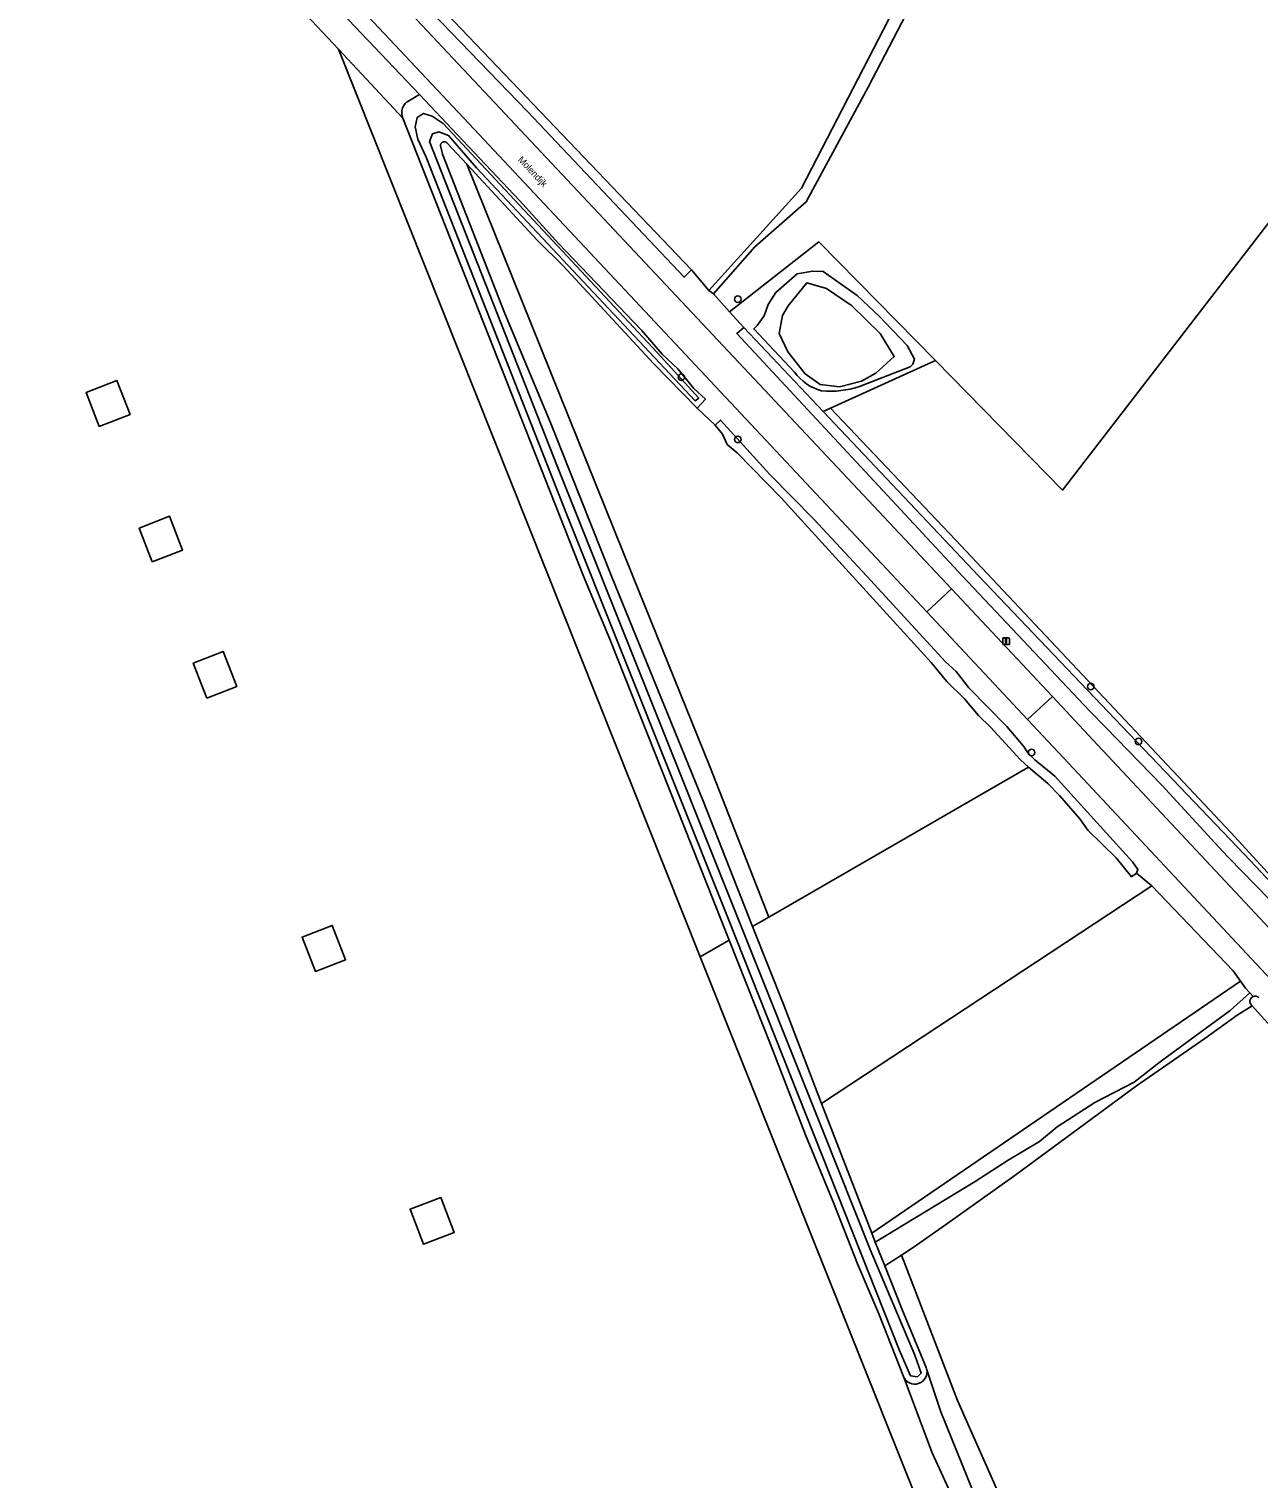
# Model space of a CAD drawing. Extents: x 164494 to 166241, y 382475 to 384495.
# Drawn here: x 165112.8 to 165297.4, y 384114.4 to 384332.1 of the extents above; entities that cross this region are included whole.
import ezdxf

# ---------------------------------------------------------------- set-up
doc = ezdxf.new("R2010")
doc.units = 0
for name, color, linetype in [('IMGEO_Boom', 7, 'Continuous'), ('IMGEO_Erf', 7, 'Continuous'), ('IMGEO_Grasland_agrarisch', 7, 'Continuous'), ('IMGEO_Grasland_overig', 7, 'Continuous'), ('IMGEO_Groenvoorziening', 7, 'Continuous'), ('IMGEO_Hek', 7, 'Continuous'), ('IMGEO_Lichtmast', 7, 'Continuous'), ('IMGEO_Loofbos', 7, 'Continuous'), ('IMGEO_Meer_plas_ven_vijver', 7, 'Continuous'), ('IMGEO_Oever', 7, 'Continuous'), ('IMGEO_Openbare_ruimte_label', 7, 'Continuous'), ('IMGEO_Pand', 7, 'Continuous'), ('IMGEO_Rijbaan_lokaal_gesloten', 7, 'Continuous'), ('IMGEO_Waterloop', 7, 'Continuous')]:
    doc.layers.add(name, color=color, linetype=linetype)

msp = doc.modelspace()

# ---------------------------------------------------------------- linework, layer by layer
at = {"layer": 'IMGEO_Boom'}
for centre in [(165219.18, 384291.57), (165210.71, 384279.85), (165219.2, 384270.52), (165272.16, 384233.41), (165279.34, 384225.17), (165263.29, 384223.52)]:
    msp.add_circle(centre, 0.489, dxfattribs=at)
at = {"layer": 'IMGEO_Erf'}
msp.add_lwpolyline([(165058.45, 383934.76), (165225.03, 384001.82), (165229.53, 384009.13), (165229.49, 384009.32), (165229.72, 384009.7), (165231.84, 384013.12), (165231.96, 384013.3), (165232.95, 384013.71), (165234.05, 384014.16), (165234.97, 384014.54), (165251.9, 384021.52), (165224.07, 384092.01), (165249.77, 384102.11), (165213.54, 384192.85), (165159.24, 384329.08), (165128.69, 384361.62), (165128.46, 384361.87), (165121.19, 384360.32), (165097.67, 384355.37)], dxfattribs=at)
for points in [[(165123.33, 384272.45), (165121.34, 384277.57), (165125.98, 384279.37), (165127.96, 384274.26)], [(165131.29, 384252.13), (165129.32, 384257.2), (165133.88, 384258.97), (165135.84, 384253.9)], [(165139.46, 384231.69), (165137.44, 384236.92), (165141.95, 384238.67), (165143.97, 384233.43)], [(165153.78, 384195.81), (165158.3, 384197.55), (165160.3, 384192.38), (165155.77, 384190.64)], [(165169.99, 384154.95), (165174.62, 384156.7), (165176.61, 384151.46), (165171.99, 384149.7)]]:
    msp.add_lwpolyline(points, close=True, dxfattribs=at)
at = {"layer": 'IMGEO_Grasland_agrarisch'}
for points in [[(165254.18, 384357.46), (165254.34, 384357.92), (165219.22, 384399.74), (165132.98, 384384.35), (165141.95, 384371.97), (165145.05, 384368.61), (165145.22, 384368.44), (165150.26, 384361.6), (165171.18, 384338.98), (165212.21, 384295.98), (165214.85, 384292.89), (165228.77, 384308.21)], [(165281.32, 384203.5), (165279.02, 384205.42), (165278.29, 384204.86), (165275.96, 384207.68), (165271.71, 384211.86), (165270.52, 384213.57), (165267.49, 384217.07), (165265.74, 384218.88), (165262.8, 384221.32), (165223.85, 384198.81), (165221.41, 384197.4), (165226.07, 384185.57), (165231.77, 384170.82)], [(165231.77, 384170.82), (165239.29, 384151.37), (165294.64, 384189.17), (165293.54, 384190.72), (165281.32, 384203.5)]]:
    msp.add_lwpolyline(points, close=True, dxfattribs=at)
for points in [[(165317.48, 384327.15), (165267.93, 384262.9), (165248.84, 384282.34), (165233.08, 384275.18), (165251.87, 384255.44), (165293.19, 384211.49), (165316.39, 384186.25)], [(165324.58, 384114.29), (165325.92, 384115.35), (165347.39, 384132.2), (165335.97, 384142.71), (165320.44, 384159.32), (165315.88, 384164.36), (165309.08, 384171.59), (165305.99, 384174.88), (165304.75, 384176.21), (165296.41, 384185.48), (165294.17, 384184.07), (165289.31, 384180.6), (165279.06, 384173.47), (165260.79, 384160), (165250.35, 384152.62), (165245.53, 384149.21), (165243.74, 384148.06), (165245.46, 384143.65), (165252.14, 384126.21), (165259.36, 384109.98)]]:
    msp.add_lwpolyline(points, dxfattribs=at)
at = {"layer": 'IMGEO_Grasland_overig'}
for points in [[(165232.02, 384274.7), (165233.08, 384275.18), (165248.84, 384282.34), (165231.34, 384300.16), (165217.95, 384289.68), (165220.11, 384287.31)], [(165233.08, 384275.18), (165232.02, 384274.7), (165255.37, 384250), (165275.8, 384228.59), (165295.27, 384208.19), (165305.21, 384197.62), (165322.53, 384178.74), (165325.13, 384175.54), (165325.83, 384175.2), (165326.06, 384175.76), (165321.54, 384180.91), (165316.39, 384186.25), (165293.19, 384211.49), (165251.87, 384255.44)], [(165247.53, 384131.01), (165249.67, 384124.52), (165256.93, 384106.64), (165258.22, 384103.1), (165258.28, 384102.33), (165257.62, 384100.16), (165260.84, 384103.1), (165261.01, 384104.04), (165260.63, 384106.52), (165259.36, 384109.98), (165252.14, 384126.21), (165245.46, 384143.65), (165243.74, 384148.06), (165241.24, 384146.44), (165243.81, 384140), (165247.47, 384131.21)]]:
    msp.add_lwpolyline(points, close=True, dxfattribs=at)
for points in [[(165227.71, 384280.63), (165221.58, 384287.11), (165222.11, 384287.59), (165223.16, 384289.09), (165223.76, 384290.79), (165224.87, 384292.55), (165228.08, 384295.36), (165230.43, 384295.79)], [(165230.43, 384295.79), (165231.99, 384295.7), (165237.12, 384292.1), (165240.45, 384288.98), (165244.61, 384284.63), (165245.69, 384282.56), (165245.46, 384281.81), (165245.08, 384281.41), (165237.47, 384278.45)]]:
    msp.add_lwpolyline(points, dxfattribs=at)
for centre, radius, start, end in [((165233.63, 384284.8), 7.24, 215.1594, 255.041), ((165233.02, 384292.32), 14.57, 265.044, 287.7993)]:
    msp.add_arc(centre, radius, start, end, dxfattribs=at)
at = {"layer": 'IMGEO_Groenvoorziening'}
for points in [[(165125.84, 384370.22), (165121.47, 384369.32), (165128.46, 384361.87), (165128.69, 384361.62), (165159.24, 384329.08), (165168.89, 384318.74), (165168.83, 384318.92), (165168.78, 384319.11), (165168.75, 384319.31), (165168.74, 384319.5), (165168.75, 384319.7), (165168.77, 384319.89), (165168.82, 384320.09), (165168.87, 384320.27), (165168.95, 384320.45), (165169.04, 384320.63), (165169.14, 384320.79), (165169.26, 384320.95), (165169.39, 384321.1), (165171.41, 384322.29)], [(165219.09, 384268.52), (165217.58, 384269.73), (165216.89, 384271.32), (165215.78, 384272.64), (165213.06, 384275.2), (165206.53, 384281.93), (165192.95, 384296.56), (165189.06, 384300.45), (165178.53, 384311.81), (165203.45, 384250), (165214.98, 384221.39), (165223.85, 384198.81), (165262.8, 384221.32), (165261.63, 384222.41), (165257.13, 384227.32), (165255.32, 384229.07), (165253.22, 384231.55), (165250.54, 384234.16), (165248.2, 384237.04), (165236.38, 384250), (165225.68, 384261.74)]]:
    msp.add_lwpolyline(points, close=True, dxfattribs=at)
for points in [[(165125.84, 384370.22), (165171.41, 384322.29), (165177.05, 384316.3), (165186.4, 384306.37), (165192.3, 384299.89), (165204.72, 384286.92), (165207.82, 384283.32), (165210.2, 384281.1), (165212.58, 384278.17), (165214.31, 384276.57), (165213.06, 384275.2), (165215.78, 384272.64), (165216.57, 384273.42), (165223.99, 384265.27), (165230.58, 384258.54), (165238.55, 384250), (165250.38, 384237.11), (165251.97, 384235.66), (165253.85, 384233.24), (165259.59, 384227.44), (165262.05, 384224.47), (165262.72, 384223.44), (165263.77, 384222.42), (165266.79, 384219.98), (165278.45, 384207.1), (165279.24, 384205.95), (165279.02, 384205.42), (165281.32, 384203.5), (165293.54, 384190.72), (165294.64, 384189.17), (165295.4, 384188.12), (165296.05, 384187.42), (165296.57, 384186.89)], [(165149.92, 384355.97), (165251.27, 384248.07), (165266.44, 384231.9), (165272.49, 384225.43), (165349.9, 384142.75), (165389.4, 384100.28)], [(165304.9, 384195.4), (165292.88, 384207.71), (165291.99, 384208.63), (165282.82, 384218.63), (165274.42, 384227.27), (165271.99, 384229.76), (165252.93, 384250), (165219.02, 384286.4), (165220.11, 384287.31), (165217.95, 384289.68), (165215.52, 384292.35), (165214.85, 384292.89), (165212.21, 384295.98), (165211.13, 384294.85), (165187.62, 384319.76), (165167.54, 384340.58)], [(165262.69, 384228.45), (165247.55, 384244.62), (165178.79, 384317.94), (165158.15, 384339.95)], [(165392.96, 384088.88), (165346.21, 384139.18), (165268.81, 384221.91), (165262.69, 384228.45)], [(165253.82, 384106.45), (165248.37, 384118.39), (165244.04, 384129.85), (165240.35, 384139.25), (165237.16, 384146.73), (165233.6, 384155.8), (165229.33, 384166.13), (165224.13, 384179.56), (165217.87, 384195.35), (165213.54, 384192.85), (165249.77, 384102.11)], [(165244.04, 384129.85), (165248.37, 384118.39), (165253.82, 384106.45)], [(165257.62, 384100.16), (165258.28, 384102.33), (165258.22, 384103.1), (165256.93, 384106.64), (165249.67, 384124.52), (165247.53, 384131.01)]]:
    msp.add_lwpolyline(points, dxfattribs=at)
for centre, radius, start, end in [((165296.85, 384186.14), 0.799, 44.3556, 111.0539), ((165245.75, 384130.53), 1.84, 201.7636, 15.0275)]:
    msp.add_arc(centre, radius, start, end, dxfattribs=at)
at = {"layer": 'IMGEO_Hek'}
for points in [[(165159.24, 384329.08), (165128.69, 384361.62)], [(165213.54, 384192.85), (165159.24, 384329.08)], [(165178.53, 384311.81), (165203.45, 384250), (165214.98, 384221.39), (165223.85, 384198.81)], [(165224.07, 384092.01), (165249.77, 384102.11), (165213.54, 384192.85)], [(165294.64, 384189.17), (165239.29, 384151.37)], [(165243.74, 384148.06), (165245.46, 384143.65), (165252.14, 384126.21), (165259.36, 384109.98)]]:
    msp.add_lwpolyline(points, dxfattribs=at)
at = {"layer": 'IMGEO_Lichtmast'}
for p, q in [((165258.96, 384239.81), (165258.96, 384240.61)), ((165258.96, 384240.61), (165258.96, 384239.81)), ((165259.06, 384240.71), (165259.85, 384240.71)), ((165259.85, 384240.71), (165259.06, 384240.71)), ((165259.95, 384240.61), (165259.95, 384239.81)), ((165259.95, 384239.81), (165259.95, 384240.61)), ((165259.85, 384239.71), (165259.06, 384239.71)), ((165259.06, 384239.71), (165259.85, 384239.71))]:
    msp.add_line(p, q, dxfattribs=at)
msp.add_lwpolyline([(165259.38, 384240.58), (165259.53, 384240.58), (165259.53, 384239.83), (165259.38, 384239.83), (165259.38, 384240.58)], dxfattribs=at)
for centre, start, end in [((165259.06, 384240.61), 90, 180), ((165259.06, 384240.61), 90, 180), ((165259.85, 384240.61), 0, 90), ((165259.85, 384240.61), 360, 90), ((165259.06, 384239.81), 180, 270), ((165259.06, 384239.81), 180, 270), ((165259.85, 384239.81), 270, 0), ((165259.85, 384239.81), 270, 0)]:
    msp.add_arc(centre, 0.1, start, end, dxfattribs=at)
at = {"layer": 'IMGEO_Loofbos'}
for points in [[(165257.7, 384359.88), (165238.75, 384323.39), (165229.45, 384306.17), (165221.72, 384299.42), (165215.52, 384292.35), (165217.95, 384289.68), (165231.34, 384300.16), (165248.84, 384282.34), (165267.93, 384262.9), (165317.48, 384327.15), (165319.12, 384329.28), (165345.49, 384364.26)], [(165296.05, 384187.42), (165293.09, 384184.78), (165282.6, 384177.08), (165278.7, 384174.04), (165272.78, 384170.96), (165267.11, 384167.33), (165264.47, 384165.1), (165259.77, 384162.29), (165254.84, 384159.1), (165239.81, 384150.02), (165240.26, 384148.89), (165241.24, 384146.44), (165243.74, 384148.06), (165245.53, 384149.21), (165250.35, 384152.62), (165260.79, 384160), (165279.06, 384173.47), (165289.31, 384180.6), (165294.17, 384184.07), (165296.41, 384185.48), (165296.32, 384185.55)], [(165296.57, 384186.89), (165296.05, 384187.42)]]:
    msp.add_lwpolyline(points, dxfattribs=at)
for points in [[(165217.87, 384195.35), (165199.96, 384240.51), (165196.02, 384250), (165168.89, 384318.74), (165159.24, 384329.08), (165213.54, 384192.85)], [(165223.85, 384198.81), (165214.98, 384221.39), (165203.45, 384250), (165178.53, 384311.81), (165175.6, 384314.93), (165175.58, 384314.98), (165175.54, 384315.01), (165175.51, 384315.05), (165175.47, 384315.08), (165175.43, 384315.11), (165175.38, 384315.14), (165175.34, 384315.16), (165175.29, 384315.17), (165175.24, 384315.18), (165175.19, 384315.19), (165175.14, 384315.2), (165175.09, 384315.2), (165175.04, 384315.19), (165174.99, 384315.18), (165174.94, 384315.17), (165174.89, 384315.15), (165174.85, 384315.13), (165174.8, 384315.1), (165174.77, 384315.07), (165174.73, 384315.04), (165174.69, 384315), (165174.66, 384314.96), (165174.63, 384314.92), (165174.61, 384314.88), (165174.59, 384314.83), (165174.57, 384314.78), (165174.56, 384314.73), (165174.55, 384314.68), (165174.55, 384314.63), (165174.55, 384314.58), (165174.56, 384314.53), (165174.57, 384314.48), (165174.58, 384314.43), (165174.86, 384313.34), (165184.22, 384289.44), (165191.12, 384272.92), (165200.21, 384250), (165213.95, 384216.36), (165221.41, 384197.4)], [(165239.29, 384151.37), (165239.81, 384150.02), (165254.84, 384159.1), (165259.77, 384162.29), (165264.47, 384165.1), (165267.11, 384167.33), (165272.78, 384170.96), (165278.7, 384174.04), (165282.6, 384177.08), (165293.09, 384184.78), (165296.05, 384187.42), (165295.4, 384188.12), (165294.64, 384189.17)]]:
    msp.add_lwpolyline(points, close=True, dxfattribs=at)
msp.add_arc((165296.85, 384186.15), 0.797, 111.1183, 228.3097, dxfattribs=at)
at = {"layer": 'IMGEO_Meer_plas_ven_vijver'}
msp.add_lwpolyline([(165240.55, 384286.42), (165236.27, 384290.64), (165232.5, 384293.18), (165229.56, 384294.02), (165226.74, 384290.56), (165225.89, 384289.13), (165225.39, 384286.42), (165226.67, 384283.66), (165229.29, 384280.35), (165231.54, 384278.74), (165234.44, 384278.42), (165237.75, 384279.25), (165239.89, 384280.47), (165242.66, 384282.95)], close=True, dxfattribs=at)
at = {"layer": 'IMGEO_Oever'}
for points in [[(165231.77, 384170.82), (165226.07, 384185.57), (165221.41, 384197.4), (165213.95, 384216.36), (165200.21, 384250), (165191.12, 384272.92), (165184.22, 384289.44), (165174.86, 384313.34), (165174.58, 384314.43), (165174.57, 384314.48), (165174.56, 384314.53), (165174.55, 384314.58), (165174.55, 384314.63), (165174.55, 384314.68), (165174.56, 384314.73), (165174.57, 384314.78), (165174.59, 384314.83), (165174.61, 384314.88), (165174.63, 384314.92), (165174.66, 384314.96), (165174.69, 384315), (165174.73, 384315.04), (165174.77, 384315.07), (165174.8, 384315.1), (165174.85, 384315.13), (165174.89, 384315.15), (165174.94, 384315.17), (165174.99, 384315.18), (165175.04, 384315.19), (165175.09, 384315.2), (165175.14, 384315.2), (165175.19, 384315.19), (165175.24, 384315.18), (165175.29, 384315.17), (165175.34, 384315.16), (165175.38, 384315.14), (165175.43, 384315.11), (165175.47, 384315.08), (165175.51, 384315.05), (165175.54, 384315.01), (165175.58, 384314.98), (165175.6, 384314.93), (165178.53, 384311.81), (165189.06, 384300.45), (165192.95, 384296.56), (165206.53, 384281.93), (165213.06, 384275.2), (165214.31, 384276.57), (165212.58, 384278.17), (165210.2, 384281.1), (165207.82, 384283.32), (165204.72, 384286.92), (165192.3, 384299.89), (165186.4, 384306.37), (165177.05, 384316.3), (165171.41, 384322.29), (165169.39, 384321.1), (165169.26, 384320.95), (165169.14, 384320.79), (165169.04, 384320.63), (165168.95, 384320.45), (165168.87, 384320.27), (165168.82, 384320.09), (165168.77, 384319.89), (165168.75, 384319.7), (165168.74, 384319.5), (165168.75, 384319.31), (165168.78, 384319.11), (165168.83, 384318.92), (165168.89, 384318.74), (165196.02, 384250), (165199.96, 384240.51), (165217.87, 384195.35), (165224.13, 384179.56), (165229.33, 384166.13), (165233.6, 384155.8), (165237.16, 384146.73), (165240.35, 384139.25), (165244.04, 384129.85)], [(165245.08, 384281.41), (165245.46, 384281.81), (165245.69, 384282.56), (165244.61, 384284.63), (165240.45, 384288.98), (165237.12, 384292.1), (165231.99, 384295.7), (165230.43, 384295.79), (165228.08, 384295.36), (165224.87, 384292.55), (165223.76, 384290.79), (165223.16, 384289.09), (165222.11, 384287.59), (165221.58, 384287.11), (165227.71, 384280.63)], [(165237.47, 384278.45), (165245.08, 384281.41)], [(165247.53, 384131.01), (165247.47, 384131.21), (165243.81, 384140), (165241.24, 384146.44), (165240.26, 384148.89), (165239.81, 384150.02), (165239.29, 384151.37), (165231.77, 384170.82)]]:
    msp.add_lwpolyline(points, dxfattribs=at)
for points in [[(165172.01, 384319.45), (165173.3, 384319.05), (165174.94, 384317.92), (165207.09, 384283.54), (165213.33, 384276.73), (165212.77, 384276.32), (165179.94, 384311.3), (165175.77, 384316.15), (165174.28, 384316.71), (165173.35, 384316.37), (165172.92, 384315.22), (165192.11, 384266.41), (165231.9, 384166.88), (165239.05, 384148.88), (165245.77, 384133.05), (165246.73, 384130.35), (165246.18, 384129.81), (165245.11, 384129.92), (165243.48, 384133.73), (165217.73, 384198.58), (165193.56, 384259.09), (165172.41, 384312.88), (165171.16, 384315.6), (165170.75, 384317.45), (165171.03, 384318.86)], [(165239.89, 384280.47), (165237.75, 384279.25), (165234.44, 384278.42), (165231.54, 384278.74), (165229.29, 384280.35), (165226.67, 384283.66), (165225.39, 384286.42), (165225.89, 384289.13), (165226.74, 384290.56), (165229.56, 384294.02), (165232.5, 384293.18), (165236.27, 384290.64), (165240.55, 384286.42), (165242.66, 384282.95)]]:
    msp.add_lwpolyline(points, close=True, dxfattribs=at)
for centre, radius, start, end in [((165233.63, 384284.8), 7.24, 215.1594, 255.041), ((165233.02, 384292.32), 14.57, 265.044, 287.7993), ((165245.75, 384130.53), 1.84, 201.7636, 15.0275)]:
    msp.add_arc(centre, radius, start, end, dxfattribs=at)
at = {"layer": 'IMGEO_Pand'}
for points in [[(165123.33, 384272.45), (165127.96, 384274.26), (165125.98, 384279.37), (165121.34, 384277.57)], [(165131.29, 384252.13), (165135.84, 384253.9), (165133.88, 384258.97), (165129.32, 384257.2)], [(165139.46, 384231.69), (165143.97, 384233.43), (165141.95, 384238.67), (165137.44, 384236.92)], [(165155.77, 384190.64), (165160.3, 384192.38), (165158.3, 384197.55), (165153.78, 384195.81)], [(165176.61, 384151.46), (165174.62, 384156.7), (165169.99, 384154.95), (165171.99, 384149.7)]]:
    msp.add_lwpolyline(points, close=True, dxfattribs=at)
at = {"layer": 'IMGEO_Rijbaan_lokaal_gesloten'}
for points in [[(165247.55, 384244.62), (165251.27, 384248.07), (165149.92, 384355.97), (165143.83, 384362.17), (165134.19, 384371.98), (165130.57, 384368.53), (165146.27, 384352.47), (165158.15, 384339.95), (165178.79, 384317.94)], [(165262.69, 384228.45), (165266.44, 384231.9), (165251.27, 384248.07), (165247.55, 384244.62)]]:
    msp.add_lwpolyline(points, close=True, dxfattribs=at)
for points in [[(165272.49, 384225.43), (165266.44, 384231.9), (165262.69, 384228.45), (165268.81, 384221.91), (165346.21, 384139.18), (165392.96, 384088.88)], [(165398.79, 384090.55), (165396.29, 384093.01), (165389.4, 384100.28), (165349.9, 384142.75), (165272.49, 384225.43)]]:
    msp.add_lwpolyline(points, dxfattribs=at)
at = {"layer": 'IMGEO_Waterloop'}
for points in [[(165143.44, 384367.1), (165143.48, 384367.05), (165149.09, 384360.52), (165167.54, 384340.58), (165187.62, 384319.76), (165211.13, 384294.85), (165212.21, 384295.98), (165171.18, 384338.98)], [(165254.18, 384357.46), (165228.77, 384308.21), (165214.85, 384292.89), (165215.52, 384292.35), (165221.72, 384299.42), (165229.45, 384306.17), (165238.75, 384323.39), (165257.7, 384359.88)], [(165296.32, 384185.55), (165296.41, 384185.48), (165304.75, 384176.21), (165305.99, 384174.88), (165306.6, 384174.74), (165306.95, 384174.83), (165307.46, 384175.23), (165307.62, 384175.74), (165307.64, 384176.13), (165306.55, 384177.22), (165304.28, 384179.68)]]:
    msp.add_lwpolyline(points, dxfattribs=at)
for points in [[(165239.05, 384148.88), (165231.9, 384166.88), (165192.11, 384266.41), (165172.92, 384315.22), (165173.35, 384316.37), (165174.28, 384316.71), (165175.77, 384316.15), (165179.94, 384311.3), (165212.77, 384276.32), (165213.33, 384276.73), (165207.09, 384283.54), (165174.94, 384317.92), (165173.3, 384319.05), (165172.01, 384319.45), (165171.03, 384318.86), (165170.75, 384317.45), (165171.16, 384315.6), (165172.41, 384312.88), (165193.56, 384259.09), (165217.73, 384198.58), (165243.48, 384133.73), (165245.11, 384129.92), (165246.18, 384129.81), (165246.73, 384130.35), (165245.77, 384133.05)], [(165232.02, 384274.7), (165220.11, 384287.31), (165219.02, 384286.4), (165252.93, 384250), (165271.99, 384229.76), (165274.42, 384227.27), (165282.82, 384218.63), (165291.99, 384208.63), (165292.88, 384207.71), (165304.9, 384195.4), (165311.96, 384187.56), (165321.36, 384177.67), (165322.53, 384178.74), (165305.21, 384197.62), (165295.27, 384208.19), (165275.8, 384228.59), (165255.37, 384250)], [(165262.72, 384223.44), (165262.05, 384224.47), (165259.59, 384227.44), (165253.85, 384233.24), (165251.97, 384235.66), (165250.38, 384237.11), (165238.55, 384250), (165230.58, 384258.54), (165223.99, 384265.27), (165216.57, 384273.42), (165215.78, 384272.64), (165216.89, 384271.32), (165217.58, 384269.73), (165219.09, 384268.52), (165225.68, 384261.74), (165236.38, 384250), (165248.2, 384237.04), (165250.54, 384234.16), (165253.22, 384231.55), (165255.32, 384229.07), (165257.13, 384227.32), (165261.63, 384222.41), (165262.8, 384221.32), (165265.74, 384218.88), (165267.49, 384217.07), (165270.52, 384213.57), (165271.71, 384211.86), (165275.96, 384207.68), (165278.29, 384204.86), (165279.02, 384205.42), (165279.24, 384205.95), (165278.45, 384207.1), (165266.79, 384219.98), (165263.77, 384222.42)]]:
    msp.add_lwpolyline(points, close=True, dxfattribs=at)
for centre, radius, start, end in [((165296.85, 384186.15), 0.797, 111.1183, 228.3097), ((165296.85, 384186.14), 0.799, 44.3556, 111.0539)]:
    msp.add_arc(centre, radius, start, end, dxfattribs=at)

# ---------------------------------------------------------------- texts
at = {"layer": 'IMGEO_Openbare_ruimte_label'}
msp.add_text('Molendijk', height=1, rotation=313.0949, dxfattribs=at).set_placement((165186.11, 384312.43))

doc.saveas('drawing.dxf')
